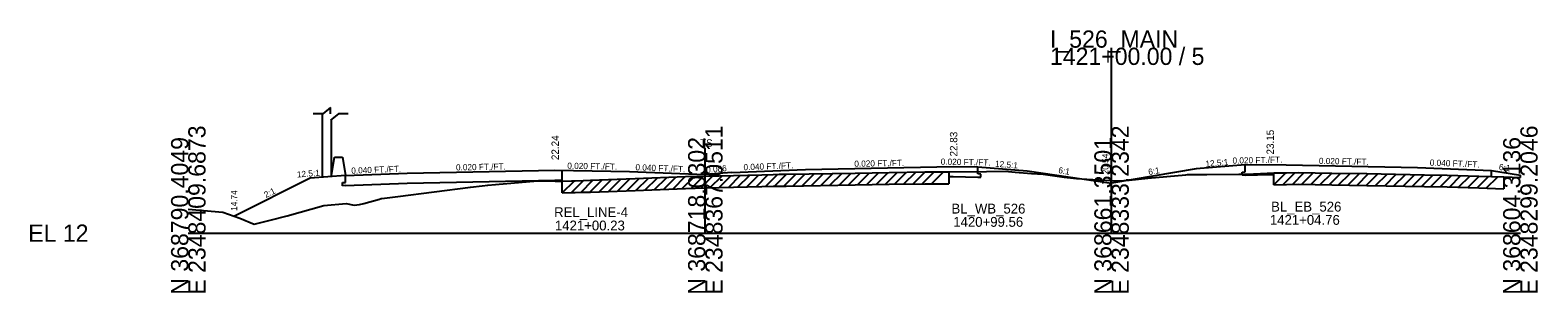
# Model space of a CAD drawing. Extents: x -170 to 2527928, y -10 to 1619750.
# Drawn here: x 3974.3 to 4219.3, y 1490.3 to 1533 of the extents above; entities that cross this region are included whole.
import ezdxf

# ---------------------------------------------------------------- set-up
doc = ezdxf.new("R2010")
doc.units = 0
for name, color, linetype in [('Default', 7, 'Continuous'), ('RD_GPK_XS_Cell', 7, 'Continuous'), ('RD_PD_NOISE-WALL-GM', 7, 'Continuous'), ('RD_XS_Base', 7, 'Continuous'), ('RD_XS_EarthShd', 7, 'Continuous'), ('RD_XS_ExGround', 7, 'Continuous'), ('RD_XS_ExPaveRet', 7, 'Continuous'), ('RD_XS_MatchLine', 7, 'Continuous'), ('RD_XS_Pave', 7, 'Continuous'), ('RD_XS_PaveShd', 7, 'Continuous'), ('RD_XS_TieSlope', 7, 'Continuous'), ('RD_XS_TX_Elev_EX', 7, 'Continuous'), ('RD_XS_TX_Slope', 7, 'Continuous'), ('RD_XS_TX_Station', 7, 'Continuous')]:
    doc.layers.add(name, color=color, linetype=linetype)

msp = doc.modelspace()

# ---------------------------------------------------------------- linework, layer by layer
at = {"layer": 'Default'}
for p, q in [((4021.88, 1519.37), (4020.3, 1519.37)), ((4023.13, 1520.4), (4021.88, 1519.37)), ((4023.13, 1519.37), (4023.13, 1520.4)), ((4024.38, 1519.37), (4023.13, 1518.34)), ((4025.98, 1519.37), (4024.38, 1519.37))]:
    msp.add_line(p, q, dxfattribs=at)
at = {"layer": 'RD_GPK_XS_Cell'}
for p, q in [((4150, 1500), (4150, 1530.11)), ((4000, 1500), (4084, 1500)), ((4084, 1500), (4150, 1500)), ((4150, 1500), (4216.42, 1500))]:
    msp.add_line(p, q, dxfattribs=at)
at = {"layer": 'RD_PD_NOISE-WALL-GM'}
for p, q in [((4021.76, 1519.37), (4021.76, 1509.05)), ((4023.26, 1509.17), (4023.26, 1518.45)), ((4023.26, 1509.36), (4023.74, 1512.36)), ((4023.74, 1512.36), (4025.08, 1512.36)), ((4025.08, 1512.36), (4025.56, 1509.36))]:
    msp.add_line(p, q, dxfattribs=at)
at = {"layer": 'RD_XS_Base'}
for p, q in [((4025.56, 1508.22), (4025.56, 1509.36)), ((4060.75, 1508.46), (4060.75, 1510.21)), ((4123.57, 1509.18), (4124.28, 1509.19)), ((4124.28, 1509.19), (4128.28, 1509.11)), ((4128.28, 1509.61), (4128.28, 1510.75)), ((4128.78, 1509.6), (4128.28, 1509.61)), ((4128.28, 1509.11), (4128.78, 1509.1)), ((4128.78, 1509.1), (4128.78, 1509.6)), ((4171.22, 1509.92), (4171.72, 1509.93)), ((4171.22, 1509.42), (4171.22, 1509.92)), ((4171.72, 1509.43), (4171.22, 1509.42)), ((4171.72, 1509.93), (4171.72, 1511.07)), ((4171.72, 1509.43), (4175.72, 1509.51)), ((4175.72, 1509.51), (4176.38, 1509.5)), ((4211.72, 1509.19), (4211.72, 1510.19)), ((4025.06, 1508.2), (4025.56, 1508.22)), ((4025.06, 1507.7), (4025.06, 1508.2)), ((4025.56, 1507.72), (4025.06, 1507.7)), ((4025.56, 1507.72), (4035.56, 1508.12)), ((4035.56, 1508.12), (4059.56, 1508.6)), ((4059.56, 1508.6), (4060.75, 1508.58))]:
    msp.add_line(p, q, dxfattribs=at)
at = {"layer": 'RD_XS_EarthShd'}
for p, q in [((4019.8, 1508.9), (4007.49, 1502.74)), ((4025.56, 1509.36), (4019.8, 1508.9)), ((4128.28, 1510.75), (4136.28, 1510.11)), ((4171.72, 1511.07), (4163.72, 1510.43))]:
    msp.add_line(p, q, dxfattribs=at)
at = {"layer": 'RD_XS_ExGround'}
msp.add_lwpolyline([(4000, 1503.89), (4005.62, 1503.41), (4008.36, 1502.44), (4010.7, 1501.48), (4013.31, 1502.13), (4016.07, 1502.83), (4022.03, 1504.48), (4025.66, 1504.8), (4026.93, 1504.52), (4027.8, 1504.65), (4028.53, 1504.83), (4031.06, 1505.52), (4031.33, 1505.6), (4031.43, 1505.62), (4034.07, 1505.95), (4045.86, 1507.45), (4047.75, 1507.67), (4048.68, 1507.81), (4049.89, 1507.91), (4056.76, 1508.5), (4058.16, 1508.48), (4059.62, 1508.45), (4060.75, 1508.46), (4062.25, 1508.5), (4062.83, 1508.51), (4064.18, 1508.55), (4065.37, 1508.58), (4072.61, 1508.86), (4080.78, 1509.18), (4084, 1509.26), (4093.19, 1509.48), (4095.01, 1509.53), (4095.98, 1509.55), (4097.15, 1509.57), (4108.37, 1509.76), (4113.85, 1509.85), (4119.65, 1509.95), (4121.45, 1509.94), (4123.57, 1509.94), (4129.66, 1510.01), (4132.71, 1510.04), (4134.32, 1509.89), (4137, 1509.7), (4138.91, 1509.55), (4142.32, 1509.11), (4144.32, 1508.85), (4145.99, 1508.74), (4150, 1508.54), (4151.06, 1508.49), (4152.88, 1508.59), (4155.87, 1508.92), (4162.06, 1509.49), (4162.32, 1509.53), (4165.49, 1509.52), (4170.66, 1509.55), (4171.96, 1509.57), (4176.38, 1509.77), (4178.42, 1509.8), (4180.37, 1509.84), (4185.8, 1509.75), (4191.48, 1509.66), (4200.85, 1509.49), (4204.52, 1509.42), (4209.65, 1509.27), (4213.75, 1509.12), (4216.42, 1509.05)], dxfattribs=at)
at = {"layer": 'RD_XS_ExPaveRet'}
for p, q in [((4072.75, 1506.95), (4074.75, 1508.94)), ((4074.25, 1507.01), (4076.25, 1509)), ((4075.75, 1507.07), (4077.75, 1509.06)), ((4077.25, 1507.13), (4079.25, 1509.12)), ((4078.75, 1507.18), (4080.75, 1509.18)), ((4080.25, 1507.24), (4082.23, 1509.22)), ((4081.75, 1507.29), (4083.72, 1509.25)), ((4083.25, 1507.32), (4085.22, 1509.29)), ((4084.75, 1507.36), (4086.72, 1509.33)), ((4086.25, 1507.4), (4088.22, 1509.36)), ((4087.75, 1507.43), (4089.72, 1509.4)), ((4089.25, 1507.47), (4091.22, 1509.43)), ((4090.75, 1507.51), (4092.72, 1509.47)), ((4092.25, 1507.54), (4094.22, 1509.51)), ((4093.75, 1507.58), (4095.72, 1509.54)), ((4095.25, 1507.62), (4097.21, 1509.57)), ((4096.75, 1507.65), (4098.7, 1509.6)), ((4098.25, 1507.67), (4100.21, 1509.62)), ((4099.75, 1507.7), (4101.71, 1509.65)), ((4101.25, 1507.72), (4103.21, 1509.68)), ((4102.75, 1507.75), (4104.71, 1509.7)), ((4104.25, 1507.78), (4106.21, 1509.73)), ((4105.75, 1507.8), (4107.71, 1509.75)), ((4107.25, 1507.83), (4109.2, 1509.78)), ((4108.75, 1507.85), (4110.7, 1509.8)), ((4110.25, 1507.88), (4112.2, 1509.83)), ((4111.75, 1507.9), (4113.7, 1509.85)), ((4113.25, 1507.93), (4115.2, 1509.88)), ((4114.75, 1507.95), (4116.7, 1509.9)), ((4116.25, 1507.98), (4118.2, 1509.92)), ((4117.75, 1508), (4119.7, 1509.95)), ((4119.25, 1508.02), (4121.17, 1509.94)), ((4120.75, 1508.03), (4122.67, 1509.94)), ((4123.57, 1509.94), (4123.57, 1508.03)), ((4176.38, 1507.85), (4178.33, 1509.8)), ((4176.38, 1507.85), (4176.38, 1509.77)), ((4177.88, 1507.87), (4179.84, 1509.83)), ((4179.38, 1507.9), (4181.31, 1509.83)), ((4180.88, 1507.92), (4182.77, 1509.8)), ((4182.38, 1507.89), (4184.27, 1509.78)), ((4183.88, 1507.87), (4185.77, 1509.75)), ((4185.38, 1507.84), (4187.27, 1509.73)), ((4186.88, 1507.82), (4188.77, 1509.7)), ((4188.38, 1507.79), (4190.27, 1509.68)), ((4189.88, 1507.77), (4191.77, 1509.66)), ((4191.38, 1507.75), (4193.26, 1509.63)), ((4192.88, 1507.72), (4194.76, 1509.6)), ((4194.38, 1507.69), (4196.26, 1509.57)), ((4195.88, 1507.66), (4197.76, 1509.54)), ((4197.38, 1507.64), (4199.26, 1509.52)), ((4198.88, 1507.61), (4200.76, 1509.49)), ((4200.38, 1507.58), (4202.27, 1509.46)), ((4201.88, 1507.55), (4203.77, 1509.44)), ((4203.38, 1507.53), (4205.26, 1509.4)), ((4204.88, 1507.49), (4206.74, 1509.35)), ((4206.38, 1507.45), (4208.24, 1509.31)), ((4207.88, 1507.4), (4209.74, 1509.26)), ((4209.38, 1507.36), (4211.24, 1509.21)), ((4210.88, 1507.31), (4212.73, 1509.16)), ((4213.75, 1509.12), (4213.75, 1507.2)), ((4060.75, 1506.54), (4062.72, 1508.51)), ((4060.75, 1506.54), (4060.75, 1508.46)), ((4060.75, 1506.54), (4062.25, 1506.58)), ((4062.25, 1506.58), (4064.23, 1508.55)), ((4062.25, 1506.58), (4062.83, 1506.59)), ((4062.83, 1506.59), (4064.18, 1506.63)), ((4063.75, 1506.62), (4065.73, 1508.59)), ((4064.18, 1506.63), (4065.37, 1506.66)), ((4065.25, 1506.66), (4067.25, 1508.65)), ((4065.37, 1506.66), (4072.61, 1506.94)), ((4066.75, 1506.72), (4068.75, 1508.71)), ((4068.25, 1506.77), (4070.25, 1508.77)), ((4069.75, 1506.83), (4071.75, 1508.83)), ((4071.25, 1506.89), (4073.25, 1508.89)), ((4072.61, 1506.94), (4080.78, 1507.26)), ((4080.78, 1507.26), (4084, 1507.34)), ((4084, 1507.34), (4093.19, 1507.57)), ((4093.19, 1507.57), (4095.01, 1507.61)), ((4095.01, 1507.61), (4095.98, 1507.63)), ((4095.98, 1507.63), (4097.15, 1507.65)), ((4097.15, 1507.65), (4108.37, 1507.85)), ((4108.37, 1507.85), (4113.85, 1507.94)), ((4113.85, 1507.94), (4119.65, 1508.03)), ((4119.65, 1508.03), (4121.45, 1508.03)), ((4121.45, 1508.03), (4123.57, 1508.03)), ((4176.38, 1507.85), (4178.42, 1507.88)), ((4178.42, 1507.88), (4180.37, 1507.93)), ((4180.37, 1507.93), (4185.8, 1507.83)), ((4185.8, 1507.83), (4191.48, 1507.74)), ((4191.48, 1507.74), (4200.85, 1507.57)), ((4200.85, 1507.57), (4204.52, 1507.51)), ((4204.52, 1507.51), (4209.65, 1507.35)), ((4209.65, 1507.35), (4213.75, 1507.2))]:
    msp.add_line(p, q, dxfattribs=at)
at = {"layer": 'RD_XS_MatchLine'}
msp.add_line((4084, 1500), (4084, 1513.78), dxfattribs=at)
at = {"layer": 'RD_XS_Pave'}
for p, q in [((4035.56, 1509.76), (4059.56, 1510.24)), ((4059.56, 1510.24), (4071.67, 1509.99)), ((4100.28, 1510.35), (4124.28, 1510.83)), ((4175.72, 1511.15), (4199.72, 1510.67))]:
    msp.add_line(p, q, dxfattribs=at)
at = {"layer": 'RD_XS_PaveShd'}
for p, q in [((4025.56, 1509.36), (4035.56, 1509.76)), ((4071.67, 1509.99), (4084, 1509.5)), ((4088.28, 1509.87), (4084, 1509.5)), ((4088.28, 1509.87), (4100.28, 1510.35)), ((4124.28, 1510.83), (4128.28, 1510.75)), ((4171.72, 1511.07), (4175.72, 1511.15)), ((4199.72, 1510.67), (4211.72, 1510.19))]:
    msp.add_line(p, q, dxfattribs=at)
at = {"layer": 'RD_XS_TieSlope'}
for p, q in [((4136.28, 1510.11), (4150, 1508.14)), ((4163.72, 1510.43), (4150, 1508.14)), ((4211.72, 1510.19), (4216.42, 1509.41)), ((4216.42, 1509.05), (4216.42, 1509.41))]:
    msp.add_line(p, q, dxfattribs=at)

# ---------------------------------------------------------------- texts
at = {"layer": 'RD_GPK_XS_Cell'}
for s, p in [('I_526_MAIN', (4140, 1530.11)), ('1421+00.00 / 5', (4140, 1527.31)), ('EL 12', (3974, 1498.6))]:
    msp.add_text(s, height=2.8, dxfattribs=at).set_placement(p)
for s, p in [('E 2348409.6873', (4002.8, 1490)), ('E 2348367.0511', (4086.8, 1490)), ('E 2348333.2342', (4152.8, 1490)), ('E 2348299.2046', (4219.22, 1490)), ('N 368790.4049', (4000, 1490)), ('N 368718.0302', (4084, 1490)), ('N 368661.3501', (4150, 1490)), ('N 368604.3136', (4216.42, 1490))]:
    msp.add_text(s, height=2.8, rotation=90, dxfattribs=at).set_placement(p)
at = {"layer": 'RD_XS_MatchLine'}
msp.add_text('TS', height=1.2, dxfattribs=at).set_placement((4083.14, 1514.03))
at = {"layer": 'RD_XS_TX_Elev_EX'}
msp.add_text('20.54', height=1, rotation=90, dxfattribs=at).set_placement((4149.5, 1509.54))
at = {"layer": 'RD_XS_TX_Slope'}
for s, rotation, p in [('0.020 FT./FT.', 358.8542, (4061.57, 1510.45)), ('0.040 FT./FT.', 2.2832, (4090.22, 1510.2)), ('0.020 FT./FT.', 1.1384, (4108.22, 1510.76)), ('0.020 FT./FT.', 358.8471, (4122.24, 1511.12)), ('12.5:1', 355.4261, (4131.04, 1510.79)), ('12.5:1', 4.5739, (4165.3, 1510.76)), ('0.020 FT./FT.', 1.1524, (4169.66, 1511.28)), ('0.020 FT./FT.', 358.8611, (4183.68, 1511.24)), ('0.040 FT./FT.', 357.7094, (4201.68, 1510.97)), ('12.5:1', 4.5739, (4017.69, 1509.02)), ('0.040 FT./FT.', 2.2906, (4026.5, 1509.64)), ('0.020 FT./FT.', 1.1458, (4043.5, 1510.17)), ('0.040 FT./FT.', 357.7094, (4072.63, 1510.21)), ('0.086', 4.9322, (4084.18, 1509.77)), ('6:1', 350.5377, (4141.3, 1509.76)), ('6:1', 9.4623, (4156.05, 1509.43)), ('6:1', 352.6182, (4212.88, 1510.27)), ('14.74', 90, (4007.94, 1503.61)), ('2:1', 26.5651, (4012.61, 1505.69))]:
    msp.add_text(s, height=1, rotation=rotation, dxfattribs=at).set_placement(p)
at = {"layer": 'RD_XS_TX_Station'}
for s, p in [(' 22.83', (4124.94, 1512)), (' 23.15', (4176.38, 1512.32)), (' 22.24', (4060.21, 1511.41))]:
    msp.add_text(s, height=1.2, rotation=90, dxfattribs=at).set_placement(p)
for s, p in [('REL_LINE-4', (4059.43, 1502.61)), ('BL_WB_526', (4123.99, 1503.18)), ('BL_EB_526', (4175.92, 1503.5)), ('1421+00.23', (4059.56, 1500.44)), ('1420+99.56', (4124.28, 1501.03)), ('1421+04.76', (4175.72, 1501.35))]:
    msp.add_text(s, height=1.6, dxfattribs=at).set_placement(p)

doc.saveas('drawing.dxf')
